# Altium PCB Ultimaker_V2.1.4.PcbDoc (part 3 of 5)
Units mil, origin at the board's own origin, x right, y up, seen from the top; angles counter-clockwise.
Board outline 6889.76 x 3110.24 mil, 4 copper layers (top, signal, Power, bot (thermal)), stack 67.717 mil thick; 574 components, 252 nets, 1322 pads, 511 vias.
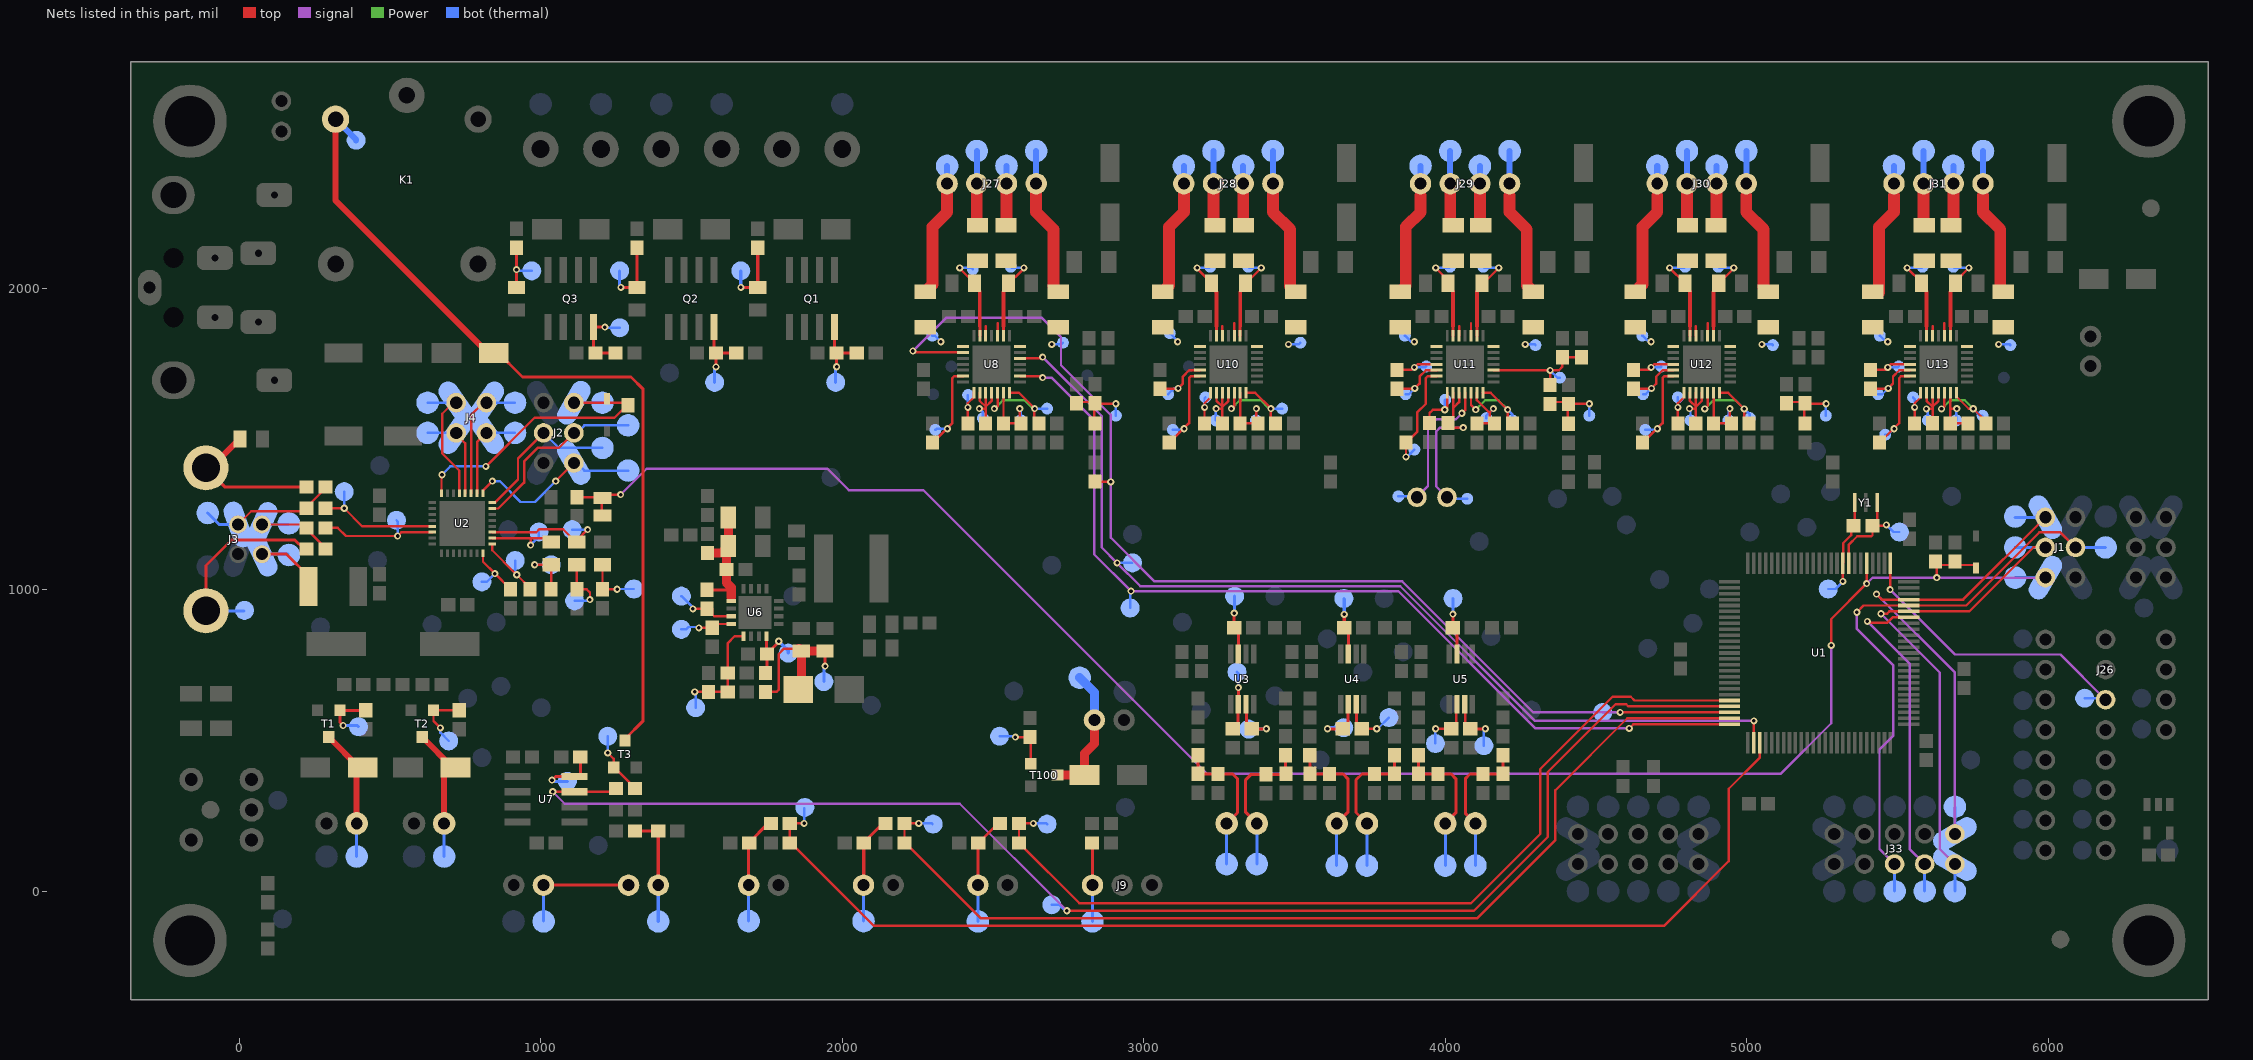
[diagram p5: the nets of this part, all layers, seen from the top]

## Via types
v1: diameter 23.62, hole 11.81, top to bot (thermal), tented bottom, 172 vias
v2: diameter 23.62, hole 11.81, top to bot (thermal), tented both sides, 104 vias
v3: diameter 39.37, hole 19.68, top to bot (thermal), tented bottom, 88 vias
v4: diameter 25.98, hole 12.99, top to bot (thermal), tented bottom, 58 vias
v5: diameter 23.62, hole 11.81, top to bot (thermal), 46 vias
v6: diameter 39.37, hole 19.68, top to bot (thermal), tented both sides, 43 vias

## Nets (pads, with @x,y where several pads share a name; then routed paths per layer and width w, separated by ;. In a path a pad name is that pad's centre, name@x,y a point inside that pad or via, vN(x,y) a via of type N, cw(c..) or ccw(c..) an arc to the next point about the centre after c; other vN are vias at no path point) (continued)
NetC41_2: C41.2 TP420.1 U10.5 | length 214.2
  top w8: C41.2@3054.14,1664.89 C41.2@3056.14,1664.89 ; C41.2@3054.64,1665.9 v2@3112.31,1665.9 ; v2(3113.97,1667.56) 3129.72,1683.31 3129.72,1706.93 3150.5,1727.71 U10.5@3186.14,1727.71
  bot (thermal) w8: TP420.1@3080.94,1647.87 3100.63,1667.56 v2(3113.97,1667.56) v2@3113.97,1665.15
NetC42_1: C42.1 TP441.1 U11.4 | length 168.6
  top w8: C42.1@3839.64,1728.89 v2@3889.44,1728.89 ; v2(3897.52,1736.97) 3907.94,1747.39 U11.4@3971.14,1747.39
  bot (thermal) w8: v2(3897.52,1736.97) 3933.82,1736.97 TP441.1@3937.01,1740.16
NetC42_2: C42.2 TP443.1 U11.5 | length 211.7
  top w8: C42.2@3839.14,1664.89 C42.2@3841.14,1664.89 ; C42.2@3839.64,1665.9 3897.31,1665.9 v2(3898.97,1667.56) 3914.72,1683.31 3914.72,1706.93 3935.5,1727.71 U11.5@3971.14,1727.71
  bot (thermal) w8: TP443.1@3868.35,1647.87 3879.29,1647.87 v2(3898.97,1667.56)
NetC43_1: C43.1 TP410.1 U8.6 | length 300.3
  top w8: C43.1@2315.64,1501.39 2315.64,1502.52 2365.64,1552.52 2365.64,1701.88 2371.78,1708.02 U8.6@2401.15,1708.02
  bot (thermal) w8: TP410.1@2309.29,1529.76 2313.23,1533.7 v2(2348.66,1533.7)
NetC44_1: C44.1 TP421.1 U10.6 | length 299.8
  top w8: C44.1@3100.64,1501.39 C44.1@3100.64,1504.52 ; C44.1@3100.63,1502.52 3150.63,1552.52 3150.63,1701.88 3156.77,1708.02 U10.6@3186.14,1708.02
  bot (thermal) w8: TP421.1@3096.69,1529.76 3129.72,1529.76 v2(3133.66,1533.7)
NetC45_1: C45.1 TP434.1 U11.6 | length 365
  top w8: C45.1@3869.64,1488.4 3871.68,1488.4 3907.72,1524.44 3907.72,1588.82 3935.63,1616.74 3935.63,1701.88 3941.77,1708.02 U11.6@3971.14,1708.02 ; v1(3869.68,1440.4) C45.1@3869.68,1487.4
  bot (thermal) w8: v1(3869.68,1440.4) 3873.47,1440.4 TP434.1@3897.64,1464.57
NetC46_2: C46.2 R69.2 R70.1 TP402.1 | length 237.9
  top w8: R70.1@2777.64,1622.39 2835.64,1622.39 R69.2@2835.64,1551.39 ; C46.2@2839,1618.39 2841.01,1616.38 v5(2907.71,1616.37)
  bot (thermal) w8: TP402.1@2907.72,1577.01 v5(2907.71,1616.37)
NetC48_2: C48.2 TP404.1 U8.8 | length 151.2
  top w8: C48.2@2416.64,1551.39 v2(2416.64,1604.56) 2416.64,1618.39 2436.58,1638.34 U8.8@2436.58,1652.91
  bot (thermal) w8: v2(2416.64,1604.56) 2416.64,1644.98 TP404.1@2417.32,1645.67
NetC49_2: C49.2 TP417.1 U10.8 | length 145.6
  top w8: C49.2@3201.64,1551.39 v2(3201.64,1604.56) 3201.64,1618.39 3221.58,1638.34 U10.8@3221.58,1652.91
  bot (thermal) w8: v2@3201.64,1605.92 v2(3201.64,1604.56) 3201.64,1634.71 TP417.1@3204.72,1637.8
NetC50_2: C50.2 R71.2 R72.1 TP430.1 | length 235.1
  top w8: R72.1@4347.64,1622.39 4405.64,1622.39 R71.2@4405.64,1551.39 ; C50.2@4411,1616.38 v5(4477.7,1616.37)
  bot (thermal) w8: TP430.1@4477.71,1577.01 v5(4477.7,1616.37)
NetC51_2: C51.2 R72.2 R78.2 TP431.1 U11.17 | length 412
  top w8: U11.17@4160.12,1727.71 v1@4347.63,1727.71 ; R72.2@4347.63,1685.89 v1(4347.63,1727.39) 4376.34,1727.39 4388.47,1739.52 R78.2@4388.47,1771.02 ; R78.2@4388.47,1771.39 C51.2@4451.46,1771.39
  bot (thermal) w8: v1(4347.63,1727.39) 4372.03,1702.99 TP431.1@4380.16,1702.99
NetC52_2: C52.2 TP432.1 U11.8 | length 196.5
  top w8: C52.2@3947.64,1552.39 3947.64,1585.43 3958.9,1596.69 v2(3998.27,1596.69) 4006.58,1605 U11.8@4006.58,1652.91 U11.8@4006.58,1638.34
  bot (thermal) w8: v2(3998.27,1596.69) 3998.27,1628.19 TP432.1@4000,1629.92
NetC68_1: C68.1 TP508.1 U12.4 | length 174.5
  top w8: C68.1@4624.64,1728.89 4674.44,1728.89 v2(4682.52,1736.97) 4692.94,1747.39 U12.4@4756.14,1747.39
  bot (thermal) w8: v2(4682.52,1736.97) 4713.35,1736.97 TP508.1@4716.54,1740.16
NetC68_2: C68.2 TP509.1 U12.5 | length 209.3
  top w8: C68.2@4624.14,1664.89 C68.2@4626.14,1664.89 ; C68.2@4624.64,1665.9 4682.31,1665.9 v2(4683.97,1667.56) 4699.72,1683.31 4699.72,1706.93 4720.5,1727.71 U12.5@4756.14,1727.71
  bot (thermal) w8: TP509.1@4655.75,1647.87 4664.29,1647.87 v2(4683.97,1667.56)
NetC69_1: C69.1 TP518.1 U13.4 | length 176.9
  top w8: C69.1@5409.64,1728.89 5459.44,1728.89 v2(5467.52,1736.97) 5477.94,1747.39 U13.4@5541.14,1747.39
  bot (thermal) w8: v2(5467.52,1736.97) 5500.75,1736.97 TP518.1@5503.94,1740.16
NetC69_2: C69.2 TP519.1 U13.5 | length 214.8
  top w8: C69.2@5409.14,1664.89 C69.2@5411.14,1664.89 ; C69.2@5409.64,1665.9 5467.31,1665.9 v2(5468.97,1667.56) 5484.72,1683.31 5484.72,1706.93 5505.5,1727.71 U13.5@5541.14,1727.71
  bot (thermal) w8: TP519.1@5435.28,1647.87 5449.29,1647.87 v2(5468.97,1667.56)
NetC70_1: C70.1 TP510.1 U12.6 | length 300.8
  top w8: C70.1@4670.64,1501.39 C70.1@4670.64,1502.4 ; C70.1@4670.63,1502.52 4720.63,1552.52 4720.63,1701.88 4726.77,1708.02 U12.6@4756.14,1708.02
  bot (thermal) w8: TP510.1@4663.62,1529.76 4699.72,1529.76 v2(4703.66,1533.7)
NetC71_1: C71.1 TP520.1 U13.6 | length 297
  top w8: C71.1@5455.64,1501.39 C71.1@5455.64,1502.4 ; C71.1@5455.63,1502.52 5505.63,1552.52 5505.63,1701.88 5511.77,1708.02 U13.6@5541.14,1708.02
  bot (thermal) w8: TP520.1@5458.9,1514.02 5468.97,1514.02 v2(5488.66,1533.7)
NetC72_2: C72.2 R93.2 R94.1 TP502.1 | length 235.3
  top w8: R94.1@5132.64,1622.39 5190.64,1622.39 R93.2@5190.64,1551.39 ; C72.2@5196,1616.38 v5(5262.7,1616.37)
  bot (thermal) w8: TP502.1@5262.05,1577.01 5262.05,1615.72 v5(5262.7,1616.37)
NetC74_2: C74.2 TP504.1 U12.8 | length 143
  top w8: C74.2@4771.64,1551.39 v2(4771.64,1604.56) 4771.64,1618.39 4791.58,1638.34 U12.8@4791.58,1652.91
  bot (thermal) w8: v2(4771.64,1604.56) TP504.1@4771.64,1637.78
NetC75_2: C75.2 TP517.1 U13.8 | length 146
  top w8: C75.2@5556.64,1551.39 v2(5556.64,1604.56) 5556.64,1618.39 5576.58,1638.34 U13.8@5576.58,1652.91
  bot (thermal) w8: TP517.1@5551.18,1637.8 5556.64,1632.34 v2(5556.64,1604.56) v2@5556.64,1605.25
NetC88_2: C88.2 R105.1 TP312.1 U6.8 | length 243.7
  top w10: R105.1@1746.3,723.77 1750.24,727.71 C88.2@1750.24,786.76 ; U6.8@1749.25,841.17 U6.8@1749.25,845.82 1749.25,787.75 C88.2@1750.24,786.76 ; v2(1789.61,828.98) 1792.45,828.98 C88.2@1750.24,786.76
  bot (thermal) w10: v2(1789.61,828.98) 1821.1,797.48 TP312.1@1821.1,789.61
NetC90_1: C90.1 R108.1 R110.2 TP313.1 U6.5 | length 387.9
  top w8: v2(1511.17,660.78) R110.2@1557.33,660.78 C90.1@1620.32,660.78 R108.1@1620.32,723.77 1620.13,723.96 1620.13,822.01 1643.94,845.82 U6.5@1672.48,845.82 U6.5@1671.22,844.56
  bot (thermal) w8: v2(1511.17,660.78) 1514.02,657.94 TP313.1@1514.02,608.5
NetC100_1: C100.1 J7.2 R19.2 R20.1 TP70.1 | length 488.4
  top w10: J7.2@3375,225 3338.16,261.84 3338.16,369.44 3356.35,387.63 R19.2@3462.02,387.63 ; R20.1@3470.64,450.9 3470.64,390.5 R19.2@3472.02,389.13
  bot (thermal) w10: TP70.1@3375,90 J7.2@3375,225
NetC101_2: C101.2 J7.1 R23.1 R24.2 TP71.1 | length 496.4
  top w10: R23.1@3180.64,450.9 3180.68,450.86 R24.2@3180.68,389.13 3180.91,388.89 C101.2@3245.64,388.89 3295.09,388.89 3310.6,373.38 3310.6,260.6 J7.1@3275,225
  bot (thermal) w10: TP71.1@3275,90 J7.1@3275,225
NetC102_1: C102.1 J11.2 R29.2 R31.1 TP72.1 | length 496.4
  top w10: J11.2@3740,225 3704.3,260.7 3704.3,369.44 3723.75,388.89 C102.1@3765.64,388.89 3831.26,388.89 R29.2@3831.5,389.13 R31.1@3831.5,450.9
  bot (thermal) w10: TP72.1@3740,85 J11.2@3740,225
NetC103_2: C103.2 J11.1 R34.1 R35.2 TP73.1 | length 497.9
  top w10: R34.1@3550.64,450.9 3550.76,450.78 R35.2@3550.76,389.13 3550.99,388.89 C103.2@3615.64,388.89 3661.23,388.89 3676.74,373.38 3676.74,261.74 J11.1@3640,225
  bot (thermal) w10: TP73.1@3640,85 J11.1@3640,225
NetC104_1: C104.1 J13.2 R37.2 R38.1 TP74.1 | length 495.5
  top w10: J13.2@4100,225 4066.5,258.5 4066.5,373.38 4082.02,388.89 C104.1@4125.64,388.89 4191.26,388.89 R37.2@4191.5,389.13 R38.1@4191.5,450.9
  bot (thermal) w10: TP74.1@4100,85 4100,90 J13.2@4100,225
NetC105_2: C105.2 J13.1 R41.1 R42.2 TP75.1 | length 494.7
  top w10: R41.1@3911.5,450.9 R42.2@3911.5,389.13 3911.73,388.89 C105.2@3975.64,388.89 4019.5,388.89 4035.01,373.38 4035.01,260.01 J13.1@4000,225
  bot (thermal) w10: TP75.1@4000,85 4000,90 J13.1@4000,225
NetC111_2: C111.2 C112.2 C113.2 L100.2 R104.2 U6.1 | length 428.7
  top w10: R104.2@1551.42,999.36 1624.25,999.36 ; U6.1@1632.13,962.94 1632.13,975.74
  top w30: L100.2@1553.39,1121.41 1598.66,1121.41 C111.2@1616.38,1139.13 ; C112.2@1622.29,1239.52 C111.2@1622.29,1145.03 C111.2@1616.38,1139.13 ; 1632.13,975.74 1632.13,1007.24 1616.38,1022.98 C113.2@1616.38,1066.29 C111.2@1616.38,1139.13
NetC114_2: C114.2 TP308.1 U6.4 | length 175.1
  top w8: v2(1524.73,873.38) C114.2@1569.14,873.38 1581.93,886.17 U6.4@1632.13,886.17
  bot (thermal) w8: TP308.1@1466.77,868.35 1482.52,868.35 1490.39,876.22 1521.89,876.22 v2(1524.73,873.38)
NetD2_1: D2.1 J2.2@1110,1620 J2.5 R5.2 TP8.1 U2.24 | length 1045.6
  top w8: U2.24@671.1,1319.41 671.1,1379.55 v1(672.8,1381.25) ; v1(818.47,1408.81) 818.81,1408.81 980,1570 1245,1570 R5.2@1288.25,1613.25 ; J2.5@1110,1625 J2.5@1110,1620 R5.2@1281.5,1620
  bot (thermal) w8: v1(672.8,1381.25) 700.36,1408.81 v1@818.47,1408.87 ; J2.5@1110,1620 TP8.1@1205,1620
NetD3_1: D3.1 R11.1 TP180.1 | length 190.6
  top w8: v2(980.24,1082.6) D3.1@1035,1082.6 R11.1@1035,1001.5
  bot (thermal) w8: v2(980.24,1082.6) TP180.1@1035,1082.6
NetD3_2: D3.2 TP179.1 U2.10 | length 259.8
  top w8: U2.10@839.41,1170.79 966.77,1170.79 ; v2(966.77,1147.88) 966.77,1170.79 ; D3.2@1021.61,1170.79 966.77,1170.79
  bot (thermal) w8: v2(966.77,1147.88) 994.33,1175.44 TP179.1@994.33,1191.18
NetD4_1: D4.1 R12.1 TP189.1 | length 205.6
  top w8: D4.1@1120,1082.6 R12.1@1120,1001.5 1152.52,1001.5 1163.62,990.39 v2@1163.62,966.86
  bot (thermal) w8: TP189.1@1112.44,962.83 1159.6,962.83 v2(1163.54,966.77)
NetD4_2: D4.2 TP190.1 U2.11 | length 409.8
  top w8: U2.11@839.41,1190.47 985.47,1190.47 995,1200 1075,1200 1117.6,1157.4 D4.2@1120,1157.4 1120,1163.31 v2(1155.75,1199.06)
  bot (thermal) w8: TP190.1@1104.57,1199.06 v2(1155.75,1199.06)
NetD5_1: D5.1 J14.2 T1.3 TP78.1 | length 439
  top w10: D5.1@398.82,410 D5.1@410,410 ; D5.1@410,400 D5.1@413.29,408.77
  top w20: T1.3@297.4,511.42 D5.1@398.82,410 ; J14.2@390,230 D5.1@390,390
  bot (thermal) w10: TP78.1@390,115 J14.2@390,230
NetD6_1: D6.1 J15.2 T2.3 TP79.1 | length 428.4
  top w20: T2.3@607.4,511.42 D6.1@708.82,410 ; J15.2@680,230 D6.1@680,400
  bot (thermal) w10: TP79.1@680,115 J15.2@680,230
NetD7_1: D7.1 R45.1 TP314.1 | length 185.7
  top w8: D7.1@1205,1082.6 R45.1@1205,1001.5 v5(1253.46,1001.5)
  bot (thermal) w8: v5(1253.46,1001.5) 1254.17,1002.2 TP314.1@1309.29,1002.2
NetD8_2: D8.2 K1.1 T3.3 TP304.1 | length 2833.5
  top w10: D8.2@825,1785 D8.2@845,1785 ; D8.2@852.5,1792.5 940,1705 1300,1705 1340,1665 1340,565 1280,505 T3.3@1280,499.29
  top w20: K1.1@320,2560.31 320,2290 D8.2@825,1785
  bot (thermal) w20: K1.1@320,2560.31 388.03,2492.28 TP304.1@388.03,2490.39
NetD10_1: D10.1 R51.1 TP316.1 | length 232.3
  top w10: v5(1663.82,2002.4) D10.1@1720,2002.4 ; D10.1@1720,2012.4 R51.1@1720,2133.5
  bot (thermal) w10: TP316.1@1663.62,2057.32 1663.62,2002.6 v5(1663.82,2002.4)
NetD11_1: D11.1 R52.1 TP318.1 | length 231.6
  top w10: v5(1266.18,2002.4) D11.1@1320,2002.4 ; D11.1@1320,2012.4 R52.1@1320,2133.5
  bot (thermal) w10: TP318.1@1262.05,2057.32 1262.05,2006.54 v5(1266.18,2002.4)
NetD12_1: D12.1 R53.1 TP320.1 | length 173.4
  top w10: D12.1@920,2012.4 v5(920,2061.26) R53.1@920,2133.5
  bot (thermal) w8: v5(920,2061.26) 923.93,2057.32 TP320.1@970.71,2057.32
NetD16_1: D16.1 R105.2 R106.2 R107.2 TP311.1 | length 556.1
  top w8: R105.2@1746.3,660.78 1781.74,660.78 1789.61,668.65 1789.61,786.76 1807.33,804.48 R107.2@1856.54,804.48
  top w10: v2(1943.15,746.3) R106.2@1943.15,796.61
  top w30: D16.1@1854.57,676.53 1864.41,686.37 R107.2@1864.41,796.61 ; R107.2@1856.54,804.48 R107.2@1864.41,796.61 ; R106.2@1943.15,796.61 R107.2@1864.41,796.61
  bot (thermal) w10: TP311.1@1939.21,695.12 1939.21,742.36 v2(1943.15,746.3)
NetD100_1: D100.1 J34.2 T100.3 TP101.1 | length 446.3
  top w30: T100.3@2713.82,385.19 D100.1@2803.39,385.19 2803.39,456.06 2836.43,489.09 J34.2@2836.43,567.51
  bot (thermal) w30: TP101.1@2787.64,708.02 2836.43,659.24 J34.2@2836.43,567.51
NetF1_1: F1.1 J3.1 TP9.1 | length 306.5
  top w10: J3.1@75.43,1117.8 157.2,1117.8 230,1045 F1.1@230,1010
  bot (thermal) w10: J3.1@75.43,1117.8 TP9.1@162.2,1117.8
NetJ2_1: J2.1 J2.4@1110,1420 TP5.1 U2.17 | length 661.8
  top w8: U2.17@808.9,1319.41 808.9,1328.9 v1(840,1360) ; v1(1050,1360) J2.1@1110,1420
  bot (thermal) w8: v1(840,1360) 864.15,1360 933.45,1290.7 980.7,1290.7 v1(1050,1360) 1003.51,1313.51 ; J2.1@1110,1420 1120,1420 1145,1395 TP5.1@1290,1395
NetJ2_3: J2.3 TP6.1 U2.15 | length 605.8
  top w8: U2.15@839.41,1269.21 859.21,1269.21 945,1355 945,1425 990,1470 1060,1470 J2.3@1110,1520
  bot (thermal) w8: J2.3@1110,1520 1120,1520 1145,1545 TP6.1@1290,1545
NetJ2_4: J2.4@1010,1520 TP7.1 U2.16 | length 523
  top w8: U2.16@839.41,1288.9 848.9,1288.9 925,1365 925,1435 J2.4@1010,1520
  bot (thermal) w8: J2.4@1010,1520 1060,1470 TP7.1@1205,1470
NetJ3_2: J3.2 R6.1 R8.2 TP10.1 | length 340
  top w8: J3.2@75.43,1215 J3.2@80.43,1220 ; J3.2@75.43,1216.22 R6.1@212.28,1216.22 ; R6.1@208.5,1220 R6.1@223.5,1205 ; R6.1@223.5,1201.5 R8.2@286.5,1138.5
  bot (thermal) w8: J3.2@75.43,1216.22 TP10.1@161.22,1216.22
NetJ3_3: J3.3 R7.1 R9.2 TP11.1 | length 450.5
  top w8: J3.3@-3.31,1216.22 40.47,1260 R7.1@215,1260 ; R7.1@223.5,1273.5 286.5,1336.5 R9.2@286.5,1345
  bot (thermal) w10: TP11.1@-104.09,1254.17 -66.14,1216.22 J3.3@-3.31,1216.22
NetJ3_5: J3.5 L1.2 R8.1 R9.1 TP168.1 | length 1134.4
  top w10: J3.5@-110,930 -110,1080 -25,1165 185,1165 213.5,1136.5 R8.1@213.5,1135 ; J3.5@-110,1404.02 -45.98,1340 R9.1@213.5,1340
  top w20: J3.5@-93.39,1404.02 L1.2@2.6,1500
  bot (thermal) w10: J3.5@-110,930 TP168.1@16.61,930
NetJ4_1: J4.1 TP66.1 U2.18 | length 304.2
  top w8: U2.18@789.21,1319.41 789.21,1489.21 810,1510 J4.1@810,1520
  bot (thermal) w8: J4.1@820,1520 TP66.1@915,1520
NetJ4_2: J4.2 TP67.1 U2.20 | length 315
  top w8: J4.2@710,1520 715,1520 749.84,1485.16 U2.20@749.84,1319.41
  bot (thermal) w8: TP67.1@625,1520 J4.2@720,1520
NetJ4_3: J4.3 TP68.1 U2.19 | length 412.4
  top w8: U2.19@769.53,1319.41 769.53,1579.53 J4.3@810,1620
  bot (thermal) w8: J4.3@820,1620 TP68.1@915,1620
NetJ4_4: J4.4 TP69.1 U2.21 | length 434.2
  top w8: J4.4@710,1620 673.52,1583.52 673.52,1451.48 708.28,1416.72 730.16,1394.84 U2.21@730.16,1319.41
  bot (thermal) w8: TP69.1@625,1620 J4.4@720,1620
NetJ5_1: J5.1 R16.1 R18.1 TP13.1 | length 352.6
  top w10: J5.1@1690,20 1690,160 1755,225 R18.1@1756.5,225
  bot (thermal) w10: TP13.1@1690,-99.21 J5.1@1690,20
NetJ6_1: J6.1 R28.1 R111.1 TP80.1 | length 356.6
  top w8: R28.1@2451.5,160 2516.5,225 R111.1@2523.5,225
  top w10: J6.1@2450,20 R28.1@2450,158.5
  bot (thermal) w10: TP80.1@2450,-100 J6.1@2450,19.21
NetJ8_1: J8.1 R25.1 R26.1 TP14.1 | length 358.3
  top w10: J8.1@2071.5,20.71 R25.1@2071.5,160 2071.5,161.5 2135,225 R26.1@2143.5,225
  bot (thermal) w10: TP14.1@2070.79,-99.21 J8.1@2070.79,20
NetJ9_1: J9.1 R30.1 TP15.1 | length 258.5
  top w10: J9.1@2830,20 R30.1@2830,158.5
  bot (thermal) w10: TP15.1@2830,-100 J9.1@2830,20
NetJ16_2: J16.2 J17.1 TP19.1 | length 401.6
  top w10: J16.2@1009.21,20 J17.1@1291.57,20
  bot (thermal) w10: TP19.1@1009.21,-99.21 J16.2@1009.21,20
NetJ17_2: J17.2 R47.1 R48.2 TP20.1 | length 377
  top w10: R47.1@1312.99,200 R48.2@1390,200 J17.2@1390,20
  bot (thermal) w10: TP20.1@1390,-100 J17.2@1390,20
NetJ27_1: J27.1 L120.2 TP46.1 | length 471
  top w39.37: J27.1@2643.28,2346.37 2643.28,2251.88 2700.36,2194.8 L120.2@2700.36,2007.24
  bot (thermal) w20: J27.1@2643.28,2346.37 TP46.1@2643.28,2454.64
NetJ27_2: J27.2 L121.2 TP47.1 | length 197.4
  top w39.37: L121.2@2543.31,2208.66 2544.85,2210.2 J27.2@2544.85,2346.37
  bot (thermal) w20: J27.2@2544.85,2346.37 TP47.1@2544.85,2405.43
NetJ27_3: J27.3 L122.2 TP48.1 | length 247
  top w39.37: J27.3@2446.43,2346.37 2446.43,2211.05 L122.2@2448.82,2208.66
  bot (thermal) w20: J27.3@2446.43,2346.37 TP48.1@2446.43,2454.64
NetJ27_4: J27.4 L123.2 TP49.1 | length 446.2
  top w39.37: L123.2@2275.59,1988.19 2298.91,2011.51 2298.91,2047.24 2298.91,2202.8 ; 2299.64,2203.52 2348,2251.88 J27.4@2348,2346.37
  bot (thermal) w20: J27.4@2348,2346.37 TP49.1@2348,2405.43
NetJ28_1: J28.1 L130.2 TP50.1 | length 471
  top w39.37: J28.1@3428.28,2346.37 3428.28,2251.88 3485.36,2194.8 L130.2@3485.36,2007.24
  bot (thermal) w20: J28.1@3428.28,2346.37 TP50.1@3428.28,2454.64
NetJ28_2: J28.2 L131.2 TP51.1 | length 194.4
  top w39.37: L131.2@3329.85,2211.05 J28.2@3329.85,2346.37
  bot (thermal) w20: J28.2@3329.85,2346.37 TP51.1@3329.85,2405.43
NetJ28_3: J28.3 L132.2 TP52.1 | length 243.6
  top w39.37: L132.2@3231.43,2211.05 J28.3@3231.43,2346.37
  bot (thermal) w20: J28.3@3231.43,2346.37 TP52.1@3231.43,2454.64
NetJ28_4: J28.4 L133.2 TP53.1 | length 445.2
  top w39.37: L133.2@3062.99,1988.19 3083.91,2009.11 3083.91,2202.8 ; 3084.63,2203.52 3132.99,2251.88 J28.4@3133,2346.37
  bot (thermal) w20: J28.4@3133,2346.37 TP53.1@3133,2405.43
NetJ29_1: J29.1 L140.2 TP54.1 | length 459.4
  top w39.37: 4213.28,2307 4213.28,2251.88 4270.36,2194.8 4270.36,2009.17 L140.2@4291.34,1988.19
  bot (thermal) w20: J29.1@4213.28,2346.37 TP54.1@4213.28,2454.64
NetJ29_2: J29.2 L141.2 TP55.1 | length 194.4
  top w39.37: L141.2@4114.85,2211.05 J29.2@4114.85,2346.37
  bot (thermal) w20: J29.2@4114.85,2346.37 TP55.1@4114.85,2405.43
NetJ29_3: J29.3 L142.2 TP56.1 | length 243.6
  top w39.37: L142.2@4016.43,2211.05 J29.3@4016.43,2346.37
  bot (thermal) w20: J29.3@4016.43,2346.37 TP56.1@4016.43,2454.64
NetJ29_4: J29.4 L143.2 TP57.1 | length 404.8
  top w39.37: L143.2@3850.39,1988.19 3868.91,2006.7 3868.91,2202.8 ; 3869.63,2203.52 3917.99,2251.88 3917.99,2307
  bot (thermal) w20: J29.4@3918,2346.37 TP57.1@3918,2405.43
NetJ30_1: J30.1 L150.2 TP58.1 | length 457.1
  top w39.37: 4998.28,2307 4998.28,2251.88 5055.36,2194.8 5055.36,2003.69 L150.2@5070.87,1988.19
  bot (thermal) w20: J30.1@4998.28,2346.37 TP58.1@4998.28,2454.64
NetJ30_2: J30.2 L151.2 TP59.1 | length 194.4
  top w39.37: L151.2@4899.85,2211.05 J30.2@4899.85,2346.37
  bot (thermal) w20: J30.2@4899.85,2346.37 TP59.1@4899.85,2405.43
NetJ30_3: J30.3 L152.2 TP60.1 | length 243.6
  top w39.37: L152.2@4801.43,2211.05 J30.3@4801.43,2346.37
  bot (thermal) w20: J30.3@4801.43,2346.37 TP60.1@4801.43,2454.64
NetJ30_4: J30.4 L153.2 TP61.1 | length 407.1
  top w39.37: L153.2@4629.92,1988.19 4653.91,2012.18 4653.91,2202.8 ; 4654.63,2203.52 4702.99,2251.88 4702.99,2307
  bot (thermal) w20: J30.4@4703,2346.37 TP61.1@4703,2405.43
NetJ31_1: J31.1 L160.2 TP62.1 | length 454.9
  top w39.37: 5783.28,2307 5783.28,2251.88 5840.36,2194.8 5840.36,1998.22 L160.2@5850.39,1988.19
  bot (thermal) w20: J31.1@5783.28,2346.37 TP62.1@5783.28,2454.64
NetJ31_2: J31.2 L161.2 TP63.1 | length 194.4
  top w39.37: L161.2@5684.85,2211.05 J31.2@5684.85,2346.37
  bot (thermal) w20: J31.2@5684.85,2346.37 TP63.1@5684.85,2405.43
NetJ31_3: J31.3 L162.2 TP64.1 | length 243.6
  top w39.37: L162.2@5586.43,2211.05 J31.3@5586.43,2346.37
  bot (thermal) w20: J31.3@5586.43,2346.37 TP64.1@5586.43,2454.64
NetJ31_4: J31.4 L163.2 TP65.1 | length 399.4
  top w39.37: L163.2@5438.91,1986 5438.91,2202.8 ; 5439.63,2203.52 5487.99,2251.88 5487.99,2307
  bot (thermal) w20: J31.4@5488,2346.37 TP65.1@5488,2405.43
NetJP3_1: JP3.1 TP428.1 U11.11 | length 512.9
  top w8: v1(4055,1584.88) v1@4057.64,1587.52 ; v1@4057.64,1587.39 v1@4057.64,1587.52 ; U11.11@4065.63,1652.91 4065.64,1595.52 v1@4057.64,1587.52
  signal w8: JP3.1@3905.75,1306.45 3942.64,1343.34 3942.64,1537.13 3970.71,1565.2 4035.31,1565.2 v1(4055,1584.88)
  bot (thermal) w8: TP428.1@3844.72,1309.29 3902.91,1309.29 JP3.1@3905.75,1306.45
NetJP3_2: JP3.2 R65.1 TP442.1 U11.9 U11.10 | length 587.7
  top w8: R65.1@4009.64,1537.39 v1(4059.64,1537.39) ; R65.1@4026.27,1571.39 U11.9@4026.26,1652.91 ; 4026.27,1602.39 4045.95,1622.08 U11.10@4045.95,1652.91
  signal w8: JP3.2@4005.75,1306.45 3970,1342.2 3970,1525 3982.39,1537.39 v1(4059.64,1537.39)
  bot (thermal) w8: JP3.2@4005.75,1306.45 4010.78,1301.42 TP442.1@4073.07,1301.42
NetL120_1: L120.1 TP411.1 U8.21 | length 39.5
  bot (thermal) w8: v2(2695.12,1813.23) 2726.61,1813.23 TP411.1@2732.28,1818.9
NetL121_1: L121.1 U8.24 | length 41.8
  top w8: U8.24@2515.32,1841.88 2515.32,1883.69
NetL122_1: L122.1 U8.26 | length 31
  top w8: U8.26@2475.95,1841.88 2475.95,1872.88
NetL123_1: L123.1 TP414.1 U8.1 | length 36.7
  bot (thermal) w8: TP414.1@2299.21,1842.52 2307.2,1842.52 v2(2327.52,1822.2)
NetL130_1: L130.1 TP422.1 U10.21 | length 41.9
  bot (thermal) w8: v2(3480.11,1813.23) 3514.02,1813.23 TP422.1@3519.68,1818.9
NetL131_1: L131.1 U10.24 | length 41.8
  top w8: U10.24@3300.32,1841.88 3300.32,1883.69
NetL132_1: L132.1 U10.26 | length 31
  top w8: U10.26@3260.95,1841.88 3260.95,1872.88
NetL133_1: L133.1 TP425.1 U10.1 | length 38.9
  bot (thermal) w8: TP425.1@3086.61,1850.39 3112.52,1824.49 v2(3112.52,1822.2)
NetL140_1: L140.1 TP435.1 U11.21 | length 35
  bot (thermal) w8: v2(4265.11,1813.23) 4297.01,1813.23 TP435.1@4299.21,1811.02
NetL141_1: L141.1 U11.24 | length 41.8
  top w8: U11.24@4085.32,1841.88 4085.32,1883.69
NetL142_1: L142.1 U11.26 | length 31
  top w8: U11.26@4045.95,1841.88 4045.95,1872.88
NetL143_1: L143.1 TP438.1 U11.1 | length 39.8
  bot (thermal) w8: TP438.1@3866.14,1842.52 3886.46,1822.2 v2(3897.52,1822.2)
NetL150_1: L150.1 TP511.1 U12.21 | length 37.4
  bot (thermal) w8: v2(5050.11,1813.23) 5084.41,1813.23 TP511.1@5086.61,1811.02
NetL151_1: L151.1 U12.24 | length 41.8
  top w8: U12.24@4870.32,1841.88 4870.32,1883.69
NetL152_1: L152.1 U12.26 | length 31
  top w8: U12.26@4830.95,1841.88 4830.95,1872.88
NetL153_1: L153.1 TP514.1 U12.1 | length 37.4
  bot (thermal) w8: TP514.1@4653.54,1842.52 4673.87,1822.2 v2(4682.52,1822.2)
NetL160_1: L160.1 TP521.1 U13.21 | length 39.8
  bot (thermal) w8: v2(5835.11,1813.23) 5871.81,1813.23 TP521.1@5874.02,1811.02
NetL161_1: L161.1 U13.24 | length 41.8
  top w8: U13.24@5655.32,1841.88 5655.32,1883.69
NetL162_1: L162.1 U13.26 | length 31
  top w8: U13.26@5615.95,1841.88 5615.95,1872.88
NetL163_1: L163.1 TP524.1 U13.1 | length 35
  bot (thermal) w8: TP524.1@5440.94,1842.52 5461.27,1822.2 v2(5467.52,1822.2)
NetQ1_4: Q1.4 R54.2 R57.1 TP317.1 | length 245
  top w10: R57.1@1975,1791.5 Q1.4@1975,1870.51 ; v5(1981.5,1739.45) R57.1@1981.5,1785 R54.2@2048.5,1785
  bot (thermal) w10: TP317.1@1978.58,1687.24 1978.58,1736.54 v5(1981.5,1739.45)
NetQ2_4: Q2.4 R55.2 R58.1 TP319.1 | length 245.6
  top w10: R58.1@1575,1791.5 Q2.4@1575,1870.51 ; v5(1581.5,1738.98) R58.1@1581.5,1785 R55.2@1648.5,1785
  bot (thermal) w10: TP319.1@1577.01,1687.24 1577.01,1734.49 v5(1581.5,1738.98)
NetQ3_4: Q3.4 R56.2 R59.1 TP321.1 | length 243.2
  top w10: v5(1213.03,1870.51) Q3.4@1175,1870.51 1175,1791.5 R59.1@1181.5,1785 R56.2@1248.5,1785
  bot (thermal) w8: v5(1213.03,1870.51) 1215.2,1868.35 TP321.1@1262.05,1868.35
NetR4_1: R4.1 TP131.1 U1.33 Y1.3 | length 376.6
  top w8: U1.33@5338.43,1087.24 5338.43,1149.24 5366.38,1177.19 5413.62,1177.19 5416.9,1180.46 R4.1@5416.9,1211.96 5459.98,1211.96 v2(5462.82,1214.8) v2@5466.77,1214.8 ; R4.1@5410,1198.5 R4.1@5420,1198.5 ; R4.1@5432.4,1205.91 Y1.3@5432.4,1283.5
  bot (thermal) w8: v2(5462.82,1214.8) 5486.44,1191.18 TP131.1@5506.14,1191.18
NetR4_2: R4.2 TP130.1 U1.34 Y1.1 | length 335.7
  top w8: v5(5318.74,1027.4) U1.34@5318.74,1087.24 ; U1.34@5320,1088.5 5320,1154.43 5346.03,1180.46 5346.03,1204.09 R4.2@5353.91,1211.96 ; R4.2@5357.6,1209.41 Y1.1@5357.6,1288.5
  bot (thermal) w8: TP130.1@5269.92,1002.2 5293.54,1002.2 v5(5318.74,1027.4)
NetR6_2: R6.2 TP169.1 U2.30 | length 449.2
  top w8: R6.2@286.5,1205 R6.2@290,1205 ; R6.2@294,1205 R6.2@290,1205 ; R6.2@304.54,1190 292,1202.54 292,1203 R6.2@290,1205 ; U2.30@640.59,1190.47 538.35,1190.47 v2(525.83,1177.95) 354.02,1177.95 326.97,1205 R6.2@290,1205
  bot (thermal) w8: TP169.1@521.89,1230 525.83,1226.06 v2(525.83,1177.95)
NetR7_2: R7.2 TP170.1 U2.29 | length 464.5
  top w8: R7.2@286.5,1270 v5(348.58,1270) 408.58,1210 U2.29@640.43,1210 ; R7.2@291.5,1255 R7.2@291.5,1271.5 ; R7.2@291.5,1265 R7.2@301.5,1255
  bot (thermal) w8: v5(348.58,1270) 348.58,1324.96 TP170.1@348.66,1325.04
NetR13_1: R13.1 TP174.1 U2.8 | length 211.2
  top w8: U2.8@808.9,1120.59 808.9,1092.6 v2(848.39,1053.11) R13.1@900,1001.5
  bot (thermal) w8: TP174.1@805.35,1025.83 821.1,1025.83 v2(848.39,1053.11)
NetR14_1: R14.1 TP175.1 U2.9 | length 239.1
  top w8: U2.9@839.41,1151.1 839.41,1130.59 912.17,1057.83 ; v2(920.7,1049.3) 965,1005 R14.1@965,1001.5
  bot (thermal) w8: TP175.1@915.59,1096.69 915.59,1054.41 v2(920.7,1049.3)
NetR21_1: R21.1 TP205.1 U3.7 | length 178.1
  top w10: R21.1@3300,873.66 v5(3300,922.05) ; U3.7@3313.7,787.32 R21.1@3313.7,859.96
  bot (thermal) w10: v5(3300,922.05) 3301.42,923.46 TP205.1@3301.42,978.58
NetR22_1: R22.1 TP201.1 U3.2 | length 180.5
  top w10: R22.1@3311.97,548.66 3311.97,618.27 U3.2@3313.7,620 v5(3313.7,674.96)
  bot (thermal) w10: TP201.1@3309.29,726.61 3313.7,722.2 v5(3313.7,674.96)
NetR22_2: R22.2 TP203.1 U3.3 | length 179.2
  top w10: U3.3@3339.29,620 3341.02,618.27 R22.2@3341.02,548.66 ; R22.2@3357.99,538.66 v5(3406.69,538.66)
  bot (thermal) w10: TP203.1@3348.66,537.64 3405.67,537.64 v5(3406.69,538.66)
NetR32_1: R32.1 TP211.1 U4.7 | length 170.3
  top w10: R32.1@3665,873.66 v5(3665,918.15) ; U4.7@3678.7,787.32 R32.1@3678.7,859.96
  bot (thermal) w10: TP211.1@3663.62,970.71 3665,969.33 v5(3665,918.15)
NetR33_1: R33.1 TP207.1 U4.2 | length 190.3
  top w10: v5(3609.53,538.66) R33.1@3660,538.66 R33.1@3673.7,552.36 ; R33.1@3676.97,555.63 3676.97,618.27 U4.2@3678.7,620
  bot (thermal) w10: v5(3609.53,538.66) 3612.96,542.1 TP207.1@3663.43,542.1
NetR33_2: R33.2 TP209.1 U4.3 | length 170.7
  top w8: R33.2@3722.99,538.66 v5(3772.83,538.66)
  top w10: U4.3@3704.29,620 3706.02,618.27 R33.2@3706.02,555.63
  bot (thermal) w8: v5(3772.83,538.66) 3775.99,538.66 TP209.1@3813.23,575.9
NetR39_1: R39.1 TP217.1 U5.7 | length 170
  top w10: R39.1@4025,873.66 v5(4025,918.7) ; U5.7@4038.7,787.32 R39.1@4038.7,859.96
  bot (thermal) w10: v5(4025,918.7) 4025,969.88 TP217.1@4025.83,970.71
NetR40_1: R40.1 TP213.1 U5.2 | length 190.4
  top w8: v5(3967.8,538.66) R40.1@4020,538.66 4036.5,555.16 4036.5,617.8 U5.2@4038.7,620
  bot (thermal) w8: TP213.1@3967.38,489.75 3967.38,538.24 v5(3967.8,538.66)
NetR40_2: R40.2 TP215.1 U5.3 | length 191.1
  top w8: R40.2@4066.29,538.66 U5.3@4066.29,620
  top w10: R40.2@4082.99,538.66 v5(4133.15,538.66)
  bot (thermal) w8: TP215.1@4128.19,482.52 4128.19,533.7 v5(4133.15,538.66)
  bot (thermal) w10: v5(4133.15,538.66) v5@4134.17,537.64
NetR43_2: R43.2 T1.1 TP218.1 | length 192.7
  top w10: v5(344.72,549.45) 334.8,559.37 T1.1@334.8,600 R43.2@420,600
  bot (thermal) w10: v5(344.72,549.45) 391.97,549.45 TP218.1@395.91,545.51
NetR44_2: R44.2 T2.1 TP219.1 | length 207.8
  top w8: v5(667.56,541.57) 644.8,564.33 T2.1@644.8,600 R44.2@730,600
  bot (thermal) w8: v5(667.56,541.57) 667.56,525.83 TP219.1@695.12,498.27
NetR46_1: R46.1 TP302.1 U7.4 | length 198.3
  top w10: v5(1037.64,368.35) 1049.29,380 U7.4@1112.72,380 ; U7.4@1130,380 1131.5,381.5 R46.1@1131.5,445
  bot (thermal) w10: v5(1037.64,368.35) 1041.57,364.41 TP302.1@1088.82,364.41
NetR60_1: R60.1 TP401.1 U8.12 U8.14 | length 437.1
  top w8: v1(2505,1600.39) 2515.32,1607.72 U8.12@2515.32,1652.91 ; U8.14@2554.69,1652.91 2586.03,1652.85 v1@2637,1601.88 ; R60.1@2636.64,1567.39 R60.1@2652.64,1551.39 R60.1@2652.64,1558.39 ; R60.1@2637,1551.39 v1@2637,1600.39
  Power w8: v1(2505,1600.39) 2532.8,1628.19 2604.57,1628.19 2632.36,1600.39 v1(2638,1600.39)
  bot (thermal) w8: v1@2638.24,1600.63 TP401.1@2679.37,1600.63
NetR61_1: R61.1 TP400.1 U8.9 U8.10 U8.11 | length 267.9
  top w8: v2(2454.96,1600.63) 2475.95,1600.63 ; U8.9@2456.27,1652.91 2456.27,1626.08 2475.95,1606.39 ; R61.1@2475.95,1551.7 2475.95,1600.63 ; U8.10@2475.95,1652.91 2475.95,1606.39 ; U8.11@2495.64,1652.91 2495.64,1626.08 2475.95,1606.39 ; 2475.95,1600.63 2475.95,1606.39
  bot (thermal) w8: v2(2454.96,1600.63) 2466.77,1588.82 TP400.1@2466.77,1569.13
NetR62_1: R62.1 TP416.1 U10.12 U10.14 | length 415.3
  top w8: v1(3290.64,1600.39) 3300.32,1607.08 U10.12@3300.32,1652.91 ; U10.14@3339.69,1652.91 3369.18,1652.85 v1(3421.64,1600.39) 3421.64,1567.39 R62.1@3437.64,1551.39 R62.1@3437.64,1558.39
  Power w8: v1(3290.64,1600.39) 3318.43,1628.19 3388.03,1628.19 3415.83,1600.39 v1(3421.64,1600.39)
  bot (thermal) w8: v1(3421.64,1600.39) 3421.87,1600.63 TP416.1@3458.9,1600.63
NetR63_1: R63.1 TP415.1 U10.9 U10.10 U10.11 | length 271.5
  top w8: v2(3239.96,1600.63) 3260.95,1600.63 ; U10.9@3241.26,1652.91 3241.27,1626.08 3260.95,1606.39 ; R63.1@3260.95,1551.7 3260.95,1606.39 ; U10.10@3260.95,1652.91 3260.95,1606.39 ; U10.11@3280.63,1652.91 3280.64,1626.08 3260.95,1606.39
  bot (thermal) w8: TP415.1@3238.43,1561.26 3238.43,1599.1 v2(3239.96,1600.63)
NetR64_1: R64.1 TP429.1 U11.12 U11.14 | length 399.9
  top w8: U11.12@4085.32,1652.91 4085.32,1612.71 v1(4101.14,1596.89) ; U11.14@4124.69,1652.91 4150.18,1652.85 v1@4206.39,1596.64 ; v1@4206.64,1596.39 4206.64,1567.39 R64.1@4222.64,1551.39 R64.1@4222.64,1558.39
  Power w8: v1(4101.14,1596.89) 4132.43,1628.19 4175.34,1628.19 v1(4206.64,1596.89)
  bot (thermal) w8: v1(4206.64,1596.89) 4222.68,1580.85 TP429.1@4222.68,1561.26
NetR74_2: R74.2 TP406.1 U8.27 | length 297.5
  top w8: v2(2389.76,2066.93) 2389.76,2064.96 2453,2001.72 R74.2@2453,1992
  top w10: U8.27@2456.27,1841.88 2456.27,1874
  top w13: R74.2@2453,1992 2456.27,1988.73 2456.27,1874
  bot (thermal) w8: v2(2389.76,2066.93) 2429.13,2066.93 TP406.1@2433.07,2062.99
NetR75_2: R75.2 TP407.1 U8.23 | length 297.9
  top w8: R75.2@2542,1995 2542,2004.6 2602.36,2064.96 v2(2602.36,2066.93)
  top w10: U8.23@2535.01,1841.88 2535.01,1874
  top w13: 2535.01,1874 2535.01,1988.01 R75.2@2542,1995
  bot (thermal) w8: TP407.1@2559.06,2070.87 2562.99,2066.93 v2(2602.36,2066.93)
NetR76_2: R76.2 TP427.1 U10.27 | length 271.2
  top w8: v2(3177.17,2066.93) 3177.17,2064.96 R76.2@3226.38,2015.75
  top w10: U10.27@3241.26,1841.88 3241.26,1874
  top w13: R76.2@3235,1994 3241.26,1987.74 3241.26,1874
  bot (thermal) w8: v2(3177.17,2066.93) 3216.54,2066.93 TP427.1@3220.47,2070.87
NetR77_2: R77.2 TP426.1 U10.23 | length 276.8
  top w8: R77.2@3340.55,2015.75 3340.55,2017.72 v2(3389.76,2066.93)
  top w10: U10.23@3320,1841.88 3320,1874
  top w13: 3320,1874 3320,1988 R77.2@3330,1998
  bot (thermal) w8: TP426.1@3346.46,2070.87 3350.39,2066.93 v2(3389.76,2066.93)
NetR79_2: R79.2 TP440.1 U11.27 | length 297.8
  top w8: v2(3968.5,2066.93) 4005.91,2029.53 4005.91,2015.75 4016,2005.65 R79.2@4016,1999
  top w10: U11.27@4026.26,1841.88 4026.26,1874
  top w13: R79.2@4016,1999 4026.26,1988.74 4026.26,1874
  bot (thermal) w8: v2(3968.5,2066.93) 4011.81,2066.93 TP440.1@4015.75,2070.87
NetR80_2: R80.2 TP439.1 U11.23 | length 311.2
  top w8: R80.2@4112,1996 4112,2007.67 4120.08,2015.75 4125.98,2015.75 v2(4177.17,2066.93)
  top w10: U11.23@4105,1841.88 4105,1874
  top w13: 4105,1874 4105,1989 R80.2@4112,1996
  bot (thermal) w8: TP439.1@4125.98,2070.87 4129.92,2066.93 v2(4177.17,2066.93)
NetR81_1: R81.1 R84.2 TP405.1 U8.13 | length 262.8
  top w8: R81.1@2534.64,1551.39 R84.2@2593.64,1551.39 2588.82,1556.2 v1(2588.82,1600.63) ; R81.1@2535.01,1541.39 U8.13@2535.01,1652.91
  bot (thermal) w8: v1(2588.82,1600.63) 2592.76,1596.69 TP405.1@2592.76,1561.26
NetR82_1: R82.1 R85.2 TP418.1 U10.13 | length 254.9
  top w8: R82.1@3319.64,1551.39 R85.2@3378.64,1551.39 ; R82.1@3320.01,1541.39 U10.13@3320,1652.91 ; R85.2@3373.81,1556.2 v1(3373.81,1600.63)
  bot (thermal) w8: TP418.1@3372.28,1561.26 3372.28,1599.1 v1(3373.81,1600.63)
NetR83_1: R83.1 R86.2 TP433.1 U11.13 | length 239.7
  top w8: R83.1@4104.64,1551.39 R86.2@4163.64,1551.39 ; U11.13@4105,1652.91 4105.01,1628.02 4147.64,1585.39 ; R86.2@4147.64,1551.39 4147.64,1585.39 ; v1(4159.68,1600.63) 4147.64,1588.58 4147.64,1585.39
  bot (thermal) w8: TP433.1@4136.06,1569.13 4136.06,1577.01 v1(4159.68,1600.63)
NetR87_1: R87.1 TP501.1 U12.12 U12.14 | length 416.1
  top w8: v1(4860.64,1599.39) 4870.32,1609.08 U12.12@4870.32,1652.91 ; U12.14@4909.64,1652.85 4938.18,1652.85 v1(4991.64,1599.39) 4991.64,1567.39 R87.1@5007.64,1551.39 R87.1@5007.64,1558.39
  Power w8: v1(4860.64,1599.39) 4889.43,1628.19 4962.84,1628.19 v1(4991.64,1599.39)
  bot (thermal) w8: v1(4991.64,1599.39) 5010.08,1580.95 TP501.1@5010.08,1569.13
NetR88_1: R88.1 TP500.1 U12.9 U12.10 U12.11 | length 272.3
  top w8: v2(4809.95,1600.63) 4830.94,1600.63 ; U12.9@4811.26,1652.91 4811.27,1626.08 4830.95,1606.39 ; R88.1@4830.95,1551.7 4830.95,1606.39 ; U12.10@4830.95,1652.91 4830.95,1606.39 ; U12.11@4850.63,1652.91 4850.64,1626.08 4830.95,1606.39
  bot (thermal) w8: v2(4809.95,1600.63) 4813.23,1597.35 TP500.1@4813.23,1561.26
NetR89_1: R89.1 TP516.1 U13.12 U13.14 | length 368.1
  top w8: v1(5645.64,1599.39) 5655.32,1607.08 U13.12@5655.32,1652.91 ; U13.14@5694.69,1652.91 5694.69,1641.19 5736,1599.88 v1@5747.71,1599.88 ; v1(5751,1599.88) 5751.15,1599.88 R89.1@5792.64,1558.39
  Power w8: v1(5645.64,1599.39) 5674.43,1628.19 5722.69,1628.19 v1(5751,1599.88)
  bot (thermal) w8: v1(5751,1599.88) 5773.87,1577.01 TP516.1@5781.73,1577.01
NetR90_1: R90.1 TP515.1 U13.9 U13.10 U13.11 | length 271.6
  top w8: v2(5595.38,1599.54) 5615.95,1599.54 ; U13.9@5596.26,1652.91 5596.27,1626.08 5615.95,1606.39 ; R90.1@5615.95,1551.7 5615.95,1599.54 ; U13.10@5615.95,1652.91 5615.95,1606.39 ; U13.11@5635.63,1652.91 5635.64,1626.08 5615.95,1606.39 ; 5615.95,1599.54 5615.95,1606.39
  bot (thermal) w8: v2(5595.38,1599.54) 5600.63,1594.29 TP515.1@5600.63,1561.26
NetR96_2: R96.2 TP506.1 U12.27 | length 305.7
  top w8: v2(4744.09,2066.93) 4793.31,2017.72 4793.31,2015.75 4804,2005.06 R96.2@4804,1996
  top w10: U12.27@4811.26,1841.88 4811.26,1874
  top w13: R96.2@4804,1996 4811.26,1988.74 4811.26,1874
  bot (thermal) w8: v2(4744.09,2066.93) 4791.34,2066.93 TP506.1@4795.28,2070.87
NetR97_2: R97.2 TP507.1 U12.23 | length 305.5
  top w8: R97.2@4898,1996 4898,2006.27 4956.69,2064.96 v2(4956.69,2066.93)
  top w10: U12.23@4890,1841.88 4890,1874
  top w13: 4890,1874 4890,1988 R97.2@4898,1996
  bot (thermal) w8: TP507.1@4905.51,2070.87 4909.45,2066.93 v2(4956.69,2066.93)
NetR98_2: R98.2 TP526.1 U13.27 | length 280.1
  top w8: v2(5531.5,2066.93) 5580.71,2017.72 R98.2@5580.71,2015.75
  top w10: U13.27@5596.26,1841.88 5596.26,1874
  top w13: R98.2@5590,1995 5596.26,1988.74 5596.26,1874
  bot (thermal) w8: v2(5531.5,2066.93) 5578.74,2066.93 TP526.1@5582.68,2070.87
NetR99_2: R99.2 TP525.1 U13.23 | length 303.2
  top w8: R99.2@5683,1996 5683,2003.87 5694.88,2015.75 5694.88,2025.59 v2(5736.22,2066.93)
  top w10: U13.23@5675,1841.88 5675,1874
  top w13: 5675,1874 5675,1988 R99.2@5683,1996
  bot (thermal) w8: TP525.1@5685.04,2070.87 5688.98,2066.93 v2(5736.22,2066.93)
NetR100_1: R100.1 R102.2 TP505.1 U12.13 | length 256.2
  top w8: R100.1@4889.64,1551.39 R102.2@4948.64,1551.39 ; R100.1@4890.01,1541.39 U12.13@4890,1652.91 ; R102.2@4943.81,1556.2 v1(4943.81,1600.63)
  bot (thermal) w8: TP505.1@4939.21,1561.26 4939.21,1596.03 v1(4943.81,1600.63)
NetR101_1: R101.1 R103.2 TP527.1 U13.13 | length 231.2
  top w8: R101.1@5674.64,1551.39 R103.2@5733.64,1551.39 ; R101.1@5675.01,1541.39 5675.01,1600.63 ; U13.13@5675,1652.91 5675.01,1600.63 ; v2(5696,1600.63) 5675.01,1600.63
  bot (thermal) w8: TP527.1@5695.12,1561.26 5695.12,1599.74 v2(5696,1600.63)
NetR104_1: R104.1 TP307.1 U6.3 | length 188
  top w8: v2(1505.05,936.37) R104.1@1551.42,936.37 ; R104.1@1569.14,936.37 1569.14,918.65 1576.03,911.76 U6.3@1632.13,911.76
  bot (thermal) w8: TP307.1@1466.77,978.58 1505.05,940.31 v2(1505.05,936.37)
NetR109_2: R109.2 T3.1 TP303.1 | length 230
  top w8: v5(1222.68,458.9) 1242.6,438.98 T3.1@1242.6,410.71 1244.37,410.71 1287.62,367.45 1287.62,367.38 1319.29,335.71 R109.2@1319.29,346.3
  bot (thermal) w8: v5(1222.68,458.9) TP303.1@1222.68,514.02
NetR120_2: R120.2 T100.1 TP315.1 | length 191.4
  top w8: v5(2574.17,511.17) R120.2@2622.29,511.17 2625.24,508.22 T100.1@2625.24,422.59
  bot (thermal) w8: TP315.1@2521.89,514.02 2571.32,514.02 v5(2574.17,511.17)
NRESET: C1.2 C11.1 D1.1 J1.2@5990,1040 J1.5 JP2.1 JP2.2 R3.1 TP1.1 U1.30 | length 6220
  top w8: C11.1@1115,1306.5 1203.03,1306.5 1203.03,1247.44 JP2.1@1222.44,1247.44 ; JP2.2@1205.47,1315 v1(1265,1315) ; v1(5280,815) 5280,902.52 v1(5397.48,1020) U1.30@5397.48,1087.24 ; v1(5630,1040) C1.2@5630,1093.5 ; C1.2@5641.81,1081.69 D1.1@5763.94,1081.69
  signal w8: v1(1265,1315) 1350.94,1400.94 1951.06,1400.94 2022,1330 ; 2021.03,1329.93 2267.93,1329.93 ; 2268.9,1330 3208.9,390 5113.13,390 5280,556.87 v1(5280,815) ; v1(5397.48,1020) 5417.48,1040 v1(5630,1040) J1.5@5990,1040
  bot (thermal) w10: TP1.1@5890,1040 J1.5@5990,1040
PA0: C13.2 R18.2 TP148.1 U1.78 | length 3912.1
  top w8: C13.2@1826.5,153.5 1836.5,153.5 2105,-115 4725,-115 4940,100 4940,340 5043.15,443.15 U1.78@5043.15,492.76 ; C13.2@1826.5,160 R18.2@1826.5,225 v2(1873.9,225)
  bot (thermal) w8: v2(1873.9,225) TP148.1@1873.9,275.47
PA1: TP149.1 U1.77 U8.19 | length 3313.4
  top w8: U8.19@2590.13,1767.08 2660.32,1767.08 v1(2664.64,1771.39) ; U1.77@5023.46,492.76 v1(5023.46,565)
  signal w8: v1(2664.64,1771.39) 2860.64,1575.39 2860.64,1139.83 v2(2911.65,1088.82) 2989.05,1011.43 3850.71,1011.43 4297.14,565 v1(5023.46,565)
  bot (thermal) w8: v2(2911.65,1088.82) TP149.1@2962.83,1088.82
PA3: TP151.1 U1.75 U8.16 | length 3153.6
  top w8: U8.16@2590.13,1708.02 v1@2660.01,1708.02 ; v1(4610,540) 4623.78,553.78 U1.75@4942.76,553.78
  signal w8: v1(2664.64,1703.39) 2694.64,1703.39 2835.64,1562.39 2835.64,1117.59 v5(2957.8,995.43) 3844.08,995.43 4299.51,540 v1(4610,540)
  bot (thermal) w8: TP151.1@2954.96,939.21 2954.96,992.58 v5(2957.8,995.43)
PA4: C18.2 R26.2 TP152.1 U1.74 | length 3362.5
  top w8: C18.2@2206.5,160 R26.2@2206.5,225 v2(2253.9,225) ; C18.2@2220,160 2220,150 2460,-90 4105,-90 4365,170 4365,335 4603.46,573.46 U1.74@4942.76,573.46
  bot (thermal) w8: v2(2253.9,225) 2297.05,225 TP152.1@2299.37,222.68
PA5: R66.1 TP153.1 U1.73 U8.2 | length 3866.7
  top w8: v1@2235.27,1786.76 U8.2@2401.15,1786.76 ; R66.1@2835,1358.03 v1@2890,1358.03 ; v1(4580,593.15) U1.73@4942.76,593.15
  signal w8: v1(2234.64,1791.39) 2345.64,1902.39 2660.64,1902.39 2725.64,1837.39 2725.64,1744.24 2890,1579.88 v1@2890,1358.03 ; v1(2890.64,1357.39) 2890.64,1172.83 3036.04,1027.43 3857.34,1027.43 4291.61,593.15 v1(4580,593.15)
  bot (thermal) w8: TP153.1@4521.89,592.76 v1@4579.61,592.76
PA6: R109.1 TP154.1 U1.72 U7.3 | length 4751.3
  top w8: v1(1040,330) U7.3@1112.72,330 1240,330 R109.1@1250,340 ; v1(2745,-65) 4095,-65 4340,180 4340,395 4565,620 4600,620 4607.17,612.83 U1.72@4942.76,612.83
  signal w8: v1(1040,330) 1080,290 2390,290 v1(2745,-65)
  bot (thermal) w8: TP154.1@2695.12,-45.04 2718.74,-45.04 2738.7,-65 v1(2745,-65)
PA7: C92.2 R111.2 TP155.1 U1.71 | length 3012.8
  top w8: v2(2633.9,225) R111.2@2586.5,225 C92.2@2586.5,160 2786.5,-40 4085,-40 4315,190 4315,405 4555,645 4615,645 4627.48,632.52 U1.71@4942.76,632.52
  bot (thermal) w8: v2(2633.9,225) 2677.05,225 TP155.1@2679.37,222.68
PB0: J33.4 TP29.1 U1.19 | length 1118.4
  top w8: v1@5400,890 5465,890 5483.11,908.11 U1.19@5537.24,908.11
  signal w8: v1(5400,895) 5540,755 5540,140 J33.4@5590,90
  bot (thermal) w10: TP29.1@5590,0 J33.4@5590,90
PB1: J1.3 J33.2 TP3.1 TP25.1 U1.20 | length 1757.6
  top w8: v1(5445,920) 5465.2,920 5472.99,927.8 U1.20@5537.24,927.8 5737.8,927.8 5950,1140 J1.3@5990,1140
  signal w8: v1(5445,920) 5640,725 5640,140 J33.2@5690,90
  bot (thermal) w10: TP25.1@5690,0 J33.2@5690,90 ; TP3.1@5890,1140 J1.3@5990,1140
PB2: J1.4@6090,1140 J33.6 TP2.1 TP33.1 U1.21 | length 1970.4
  top w8: v1(5365,925) 5387.48,947.48 U1.21@5537.24,947.48 5727.48,947.48 5970,1190 6040,1190 J1.4@6090,1140
  signal w8: v1(5365,925) 5365,870 5486.06,748.94 5486.06,516.06 5440,470 5440,140 J33.6@5490,90
  bot (thermal) w10: TP33.1@5490,0 J33.6@5490,90 ; J1.4@6090,1140 TP2.1@6190,1140
PB3: J1.1 J1.4@5990,1240 J33.1 TP4.1 TP23.1 U1.22 | length 1779.5
  top w8: v1@5434.33,990 5434.33,980.67 5447.83,967.17 U1.22@5537.24,967.17 5717.17,967.17 J1.1@5990,1240
  signal w8: v1@5434.33,990 5434.33,980.67 5690,725 J33.1@5690,190
  bot (thermal) w10: J33.1@5690,190 TP23.1@5690,280 ; TP4.1@5890,1240 J1.1@5990,1240
  other v1: 5430,985
PB7: J26.3 TP113.1 U1.26 | length 1020.2
  top w8: v1(5475,1000) U1.26@5475,1058.78 ; U1.26@5475,1065 5476.22,1065 U1.26@5476.22,1087.24
  signal w8: v1(5475,1000) 5690,785 6040,785 J26.3@6190,635
  bot (thermal) w8: TP113.1@6120.32,640 6185,640 J26.3@6190,635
